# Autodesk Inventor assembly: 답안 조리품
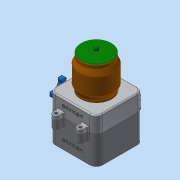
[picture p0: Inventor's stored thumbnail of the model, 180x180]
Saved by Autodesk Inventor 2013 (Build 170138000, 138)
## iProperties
Created: 2018-01
Part Number: 답안 조리품
Document SubType Name: Assembly
Designer: dgall
Author: dgall
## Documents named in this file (9)
- C:\Users\dgall\Desktop\480107V1009\답안 조리품.iam
- C:\Users\dgall\Desktop\480107V1009\본체.ipt
- C:\Users\dgall\Desktop\480107V1009\본체커버.ipt
- C:\Users\dgall\Desktop\480107V1009\볼트 M3x12.ipt
- C:\Users\dgall\Desktop\480107V1009\볼트 M4x12.ipt
- C:\Users\dgall\Desktop\480107V1009\용기.ipt
- C:\Users\dgall\Desktop\480107V1009\용기캡.ipt
- C:\Users\dgall\Desktop\480107V1009\핸들.ipt
- C:\Users\dgall\Desktop\480107V1009\핸들축.ipt
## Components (2 placed, 2 different names)
1. 핸들:1
2. 핸들축:1
